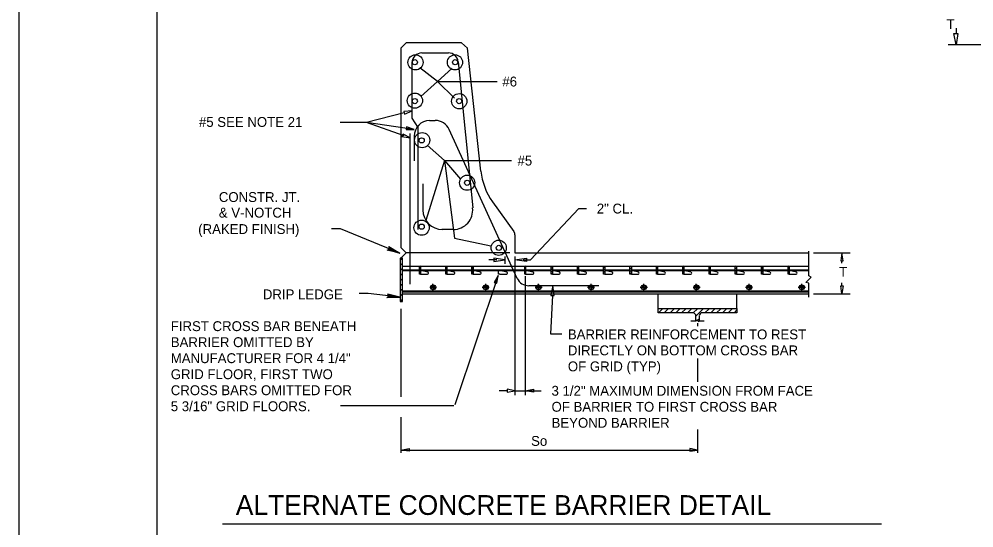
# Model space of a CAD drawing. Extents: x -24512 to -22484, y 4569 to 6351.
# Drawn here: x -24179.8 to -23889.5, y 5907.1 to 6061.6 of the extents above; entities that cross this region are included whole.
import ezdxf

# ---------------------------------------------------------------- set-up
doc = ezdxf.new("R2010")
doc.units = 0
for name, color, linetype in [('10', 7, 'Continuous'), ('11', 7, 'Continuous'), ('2', 7, 'Continuous'), ('4', 7, 'Continuous'), ('5', 7, 'Continuous'), ('8', 7, 'Continuous'), ('PLT-BNDY', 7, 'Continuous')]:
    doc.layers.add(name, color=color, linetype=linetype)

# ---------------------------------------------------------------- blocks, each defined once
blk = doc.blocks.new('JUQ000')
at = {"layer": '4'}
for p, q in [((71.0975, 21.771125), (71.421875, 22.095625)), ((71.237875, 21.6265), (71.566625, 21.95525))]:
    blk.add_line(p, q, dxfattribs=at)
blk = doc.blocks.new('JUQ002')
at = {"layer": '4'}
for p, q in [((72.87075, 24.39975), (72.993375, 24.522375)), ((72.87075, 24.114625), (73.021875, 24.265875)), ((72.87075, 23.8295), (73.021875, 23.98075)), ((72.87075, 23.544375), (73.021875, 23.695625))]:
    blk.add_line(p, q, dxfattribs=at)
blk = doc.blocks.new('JUQ004')
at = {"layer": '4'}
for p, q in [((69.644875, 24.310375), (69.796125, 24.4615)), ((69.644875, 24.02525), (69.796125, 24.176375)), ((69.644875, 23.740125), (69.796125, 23.89125)), ((69.70425, 23.514375), (69.796125, 23.60625))]:
    blk.add_line(p, q, dxfattribs=at)
blk = doc.blocks.new('JUQ003')
at = {"layer": '4'}
for p, q in [((89.35625, 63.69525), (89.860375, 64.19925)), ((90.069125, 63.69525), (90.573125, 64.19925)), ((90.781875, 63.69525), (91.285875, 64.19925)), ((91.49475, 63.69525), (91.99875, 64.19925)), ((92.2075, 63.69525), (92.7115, 64.19925)), ((92.920375, 63.69525), (93.424375, 64.19925)), ((93.628875, 63.691), (94.137125, 64.19925)), ((93.972625, 63.321875), (94.85, 64.19925)), ((95.05875, 63.69525), (95.56275, 64.19925)), ((95.7715, 63.69525), (96.275625, 64.19925)), ((96.484375, 63.69525), (96.988375, 64.19925)), ((97.197125, 63.69525), (97.70125, 64.19925)), ((97.91, 63.69525), (98.414, 64.19925)), ((98.62275, 63.69525), (99.014, 64.0865)), ((94.121125, 62.757625), (94.377, 63.013375))]:
    blk.add_line(p, q, dxfattribs=at)
blk = doc.blocks.new('JUQ001')
at = {"layer": '4'}
for p, q in [((66.419125, 24.506), (66.4355, 24.522375)), ((66.419125, 24.220875), (66.570375, 24.372125)), ((66.419125, 23.93575), (66.570375, 24.087)), ((66.419125, 23.650625), (66.570375, 23.801875)), ((66.567875, 23.514375), (66.570375, 23.51675))]:
    blk.add_line(p, q, dxfattribs=at)
blk = doc.blocks.new('_X')
at = {"layer": '4'}
for p, q in [((63.193375, 24.416625), (63.299125, 24.522375)), ((63.193375, 24.1315), (63.3445, 24.282625)), ((63.193375, 23.846375), (63.3445, 23.9975)), ((63.193375, 23.56125), (63.3445, 23.712375))]:
    blk.add_line(p, q, dxfattribs=at)

msp = doc.modelspace()

# ---------------------------------------------------------------- linework, layer by layer
at = {"layer": '10'}
for p, q in [((-23894.94, 6058.82), (-23894.94, 6057.27)), ((-23886.34, 6053.78), (-23897.31, 6053.78)), ((-24052.61, 6042.62), (-24057.96, 6046.8)), ((-24052.61, 6042.62), (-24048.18, 6046.62)), ((-24052.61, 6042.62), (-24057.6, 6038.13)), ((-24052.61, 6042.62), (-24034.39, 6042.62)), ((-24052.61, 6042.62), (-24047.44, 6037.57)), ((-24062.68, 6033.11), (-24074.15, 6030.24)), ((-24074.15, 6030.24), (-24082.14, 6030.24)), ((-24074.15, 6030.24), (-24076.52, 6030.24)), ((-24059.72, 6028.07), (-24074.15, 6030.24)), ((-24062.68, 6026.13), (-24074.15, 6030.24)), ((-24054.99, 6030.81), (-24053.26, 6030.81)), ((-24050.4, 6018.63), (-24055.75, 6023.36)), ((-24050.4, 6018.63), (-24056.12, 6000.47)), ((-24050.4, 6018.63), (-24030.09, 6018.63)), ((-24050.4, 6018.63), (-24045.6, 6013.02)), ((-24050.4, 6018.63), (-24047.44, 5995.12)), ((-24024.28, 5988.47), (-24009.57, 6004.13)), ((-24009.57, 6004.13), (-24007.32, 6004.13)), ((-24082.04, 5997.9), (-24084.78, 5997.9)), ((-24064.03, 5990.55), (-24082.04, 5997.9)), ((-24047.44, 5995.12), (-24036.37, 5992.72)), ((-23938.25, 5990.59), (-23927.15, 5990.59)), ((-24034.5, 5988.47), (-24037, 5988.47)), ((-24032.13, 5989.51), (-24032.13, 5987.23)), ((-24029.02, 5989.47), (-24029.02, 5947.45)), ((-24026.52, 5988.47), (-24024.28, 5988.47)), ((-23929.64, 5987.48), (-23929.64, 5988.23)), ((-24034.18, 5983.7), (-24047.28, 5944.42)), ((-24025.9, 5983.49), (-24025.9, 5947.45)), ((-24054.45, 5980.12), (-24054.95, 5980.12)), ((-24053.58, 5980.12), (-24054.2, 5980.12)), ((-24053.96, 5980.74), (-24053.96, 5981.24)), ((-24053.96, 5979.87), (-24053.96, 5980.37)), ((-24053.96, 5979.12), (-24053.96, 5979.5)), ((-24052.83, 5980.12), (-24053.33, 5980.12)), ((-24038.49, 5980.12), (-24038.99, 5980.12)), ((-24037.62, 5980.12), (-24038.12, 5980.12)), ((-24037.87, 5980.74), (-24037.87, 5981.24)), ((-24037.87, 5979.87), (-24037.87, 5980.37)), ((-24037.87, 5979.12), (-24037.87, 5979.5)), ((-24036.87, 5980.12), (-24037.25, 5980.12)), ((-24022.41, 5980.12), (-24022.91, 5980.12)), ((-24021.66, 5980.12), (-24022.16, 5980.12)), ((-24021.91, 5980.74), (-24021.91, 5981.24)), ((-24021.91, 5979.87), (-24021.91, 5980.37)), ((-24021.91, 5979.12), (-24021.91, 5979.5)), ((-24020.79, 5980.12), (-24021.29, 5980.12)), ((-24006.45, 5980.12), (-24006.95, 5980.12)), ((-24005.58, 5980.12), (-24006.08, 5980.12)), ((-24005.83, 5980.74), (-24005.83, 5981.24)), ((-24005.83, 5979.87), (-24005.83, 5980.37)), ((-24005.83, 5979.12), (-24005.83, 5979.5)), ((-24004.83, 5980.12), (-24005.33, 5980.12)), ((-23990.49, 5980.12), (-23990.99, 5980.12)), ((-23989.62, 5980.12), (-23990.12, 5980.12)), ((-23989.87, 5980.74), (-23989.87, 5981.24)), ((-23989.87, 5979.87), (-23989.87, 5980.37)), ((-23989.87, 5979.12), (-23989.87, 5979.5)), ((-23988.74, 5980.12), (-23989.37, 5980.12)), ((-23974.4, 5980.12), (-23974.9, 5980.12)), ((-23973.53, 5980.12), (-23974.16, 5980.12)), ((-23973.91, 5980.74), (-23973.91, 5981.24)), ((-23973.91, 5979.87), (-23973.91, 5980.37)), ((-23973.91, 5979.12), (-23973.91, 5979.5)), ((-23972.78, 5980.12), (-23973.28, 5980.12)), ((-23958.44, 5980.12), (-23958.94, 5980.12)), ((-23957.57, 5980.12), (-23958.2, 5980.12)), ((-23957.82, 5980.74), (-23957.82, 5981.24)), ((-23957.82, 5979.87), (-23957.82, 5980.37)), ((-23957.82, 5979.12), (-23957.82, 5979.5)), ((-23956.82, 5980.12), (-23957.32, 5980.12)), ((-23942.36, 5980.12), (-23942.98, 5980.12)), ((-23941.61, 5980.12), (-23942.11, 5980.12)), ((-23941.86, 5980.74), (-23941.86, 5981.24)), ((-23941.86, 5979.87), (-23941.86, 5980.37)), ((-23941.86, 5979.12), (-23941.86, 5979.5)), ((-23940.74, 5980.12), (-23941.24, 5980.12)), ((-23929.64, 5980.62), (-23929.64, 5981.49)), ((-24073.66, 5978.25), (-24076.4, 5978.25)), ((-24064.03, 5977.16), (-24073.66, 5978.25)), ((-24017.61, 5977.63), (-24018.23, 5966.03)), ((-23938.25, 5978.13), (-23927.15, 5978.13)), ((-24063.68, 5973.66), (-24063.68, 5946.93)), ((-23973.53, 5969.27), (-23973.53, 5968.4)), ((-24018.23, 5966.03), (-24014.74, 5966.03)), ((-23973.53, 5958.55), (-23973.53, 5951.44)), ((-24031.39, 5948.7), (-24033.88, 5948.7)), ((-24029.02, 5948.7), (-24021.04, 5948.7)), ((-24047.62, 5944.19), (-24082.03, 5944.19)), ((-24063.68, 5940.76), (-24063.68, 5929.87)), ((-23973.53, 5936.98), (-23973.53, 5929.87)), ((-24063.68, 5930.74), (-23973.53, 5930.74))]:
    msp.add_line(p, q, dxfattribs=at)
for points in [[(-23895.64, 6057.27), (-23894.42, 6057.27), (-23894.94, 6053.78)], [(-24062.81, 6033.49), (-24062.56, 6032.74), (-24060.31, 6033.74)], [(-24061.98, 6028.89), (-24062.06, 6028.02), (-24059.67, 6028.06)], [(-24063.02, 6026.7), (-24063.4, 6025.95), (-24060.9, 6025.57)], [(-23930.02, 5988.23), (-23929.27, 5988.23), (-23929.64, 5990.59)], [(-24035.45, 5989), (-24035.45, 5987.95), (-24032.13, 5988.47)], [(-24025.53, 5989), (-24025.53, 5987.95), (-24029.02, 5988.47)], [(-24035.33, 5981.6), (-24034.53, 5981.36), (-24034.18, 5983.7)], [(-24018.1, 5977.63), (-24017.11, 5977.63), (-24017.48, 5980.74)], [(-23930.02, 5980.62), (-23929.27, 5980.62), (-23929.64, 5978.13)], [(-24031.39, 5949.2), (-24031.39, 5948.33), (-24029.02, 5948.7)], [(-24023.41, 5949.2), (-24023.41, 5948.33), (-24025.9, 5948.7)], [(-24061.19, 5931.24), (-24061.19, 5930.37), (-24063.68, 5930.74)], [(-23975.9, 5931.24), (-23975.9, 5930.37), (-23973.53, 5930.74)]]:
    msp.add_lwpolyline(points, close=True, dxfattribs=at)
for points in [[(-24067.27, 5992.37), (-24067.24, 5992.07), (-24064.03, 5990.55), (-24067.27, 5992.37), (-24067.38, 5992.59), (-24064.03, 5990.55), (-24067.38, 5991.73), (-24067.6, 5991.53), (-24064.03, 5990.55), (-24067.85, 5991.44), (-24067.6, 5991.53)], [(-24067.64, 5978.03), (-24067.53, 5977.75), (-24064.03, 5977.16), (-24067.64, 5978.03), (-24067.81, 5978.22), (-24064.03, 5977.16), (-24067.57, 5977.38), (-24067.73, 5977.13), (-24064.03, 5977.16), (-24067.95, 5976.98), (-24067.73, 5977.13)]]:
    msp.add_lwpolyline(points, dxfattribs=at)
for centre in [(-24059.26, 6048.46), (-24047.26, 6048.46), (-24059.44, 6036.83), (-24045.97, 6036.65), (-24057.23, 6024.84), (-24043.57, 6011.91), (-24057.41, 5998.25), (-24033.97, 5992.16)]:
    msp.add_circle(centre, 2.31, dxfattribs=at)
for centre, radius, start, end in [((-24057.31, 6048.32), 3, 90, 180), ((-24049.26, 6048.32), 3, 5.6952, 90), ((-24054.84, 6026.02), 4.8, 91.8539, 180), ((-24053.3, 6026.01), 4.8, 26.0753, 89.5289), ((-24024.78, 5984.62), 4, 206.0755, 270)]:
    msp.add_arc(centre, radius, start, end, dxfattribs=at)
at = {"layer": '11'}
msp.add_line((-23917.58, 5908.21), (-24117.88, 5908.21), dxfattribs=at)
at = {"layer": '2'}
msp.add_line((-24137.79, 5772.04), (-24137.79, 6334.63), dxfattribs=at)
at = {"layer": '4'}
for p, q in [((-24063.94, 5988.48), (-24063.24, 5989.03)), ((-24063.94, 5986.92), (-24063.24, 5987.47)), ((-24063.94, 5985.37), (-24063.24, 5985.92)), ((-24063.94, 5983.81), (-24063.24, 5984.36)), ((-24063.94, 5982.25), (-24063.24, 5982.8)), ((-24063.94, 5980.7), (-24063.24, 5981.25)), ((-24063.94, 5979.14), (-24063.24, 5979.69)), ((-24063.94, 5977.59), (-24063.24, 5978.14)), ((-24063.94, 5976.03), (-24063.24, 5976.58))]:
    msp.add_line(p, q, dxfattribs=at)
at = {"layer": '5'}
for p, q in [((-24029.02, 5990.59), (-23939.74, 5990.59)), ((-24063.18, 5988.97), (-24063.88, 5988.97)), ((-24063.88, 5988.97), (-24063.88, 5975.81)), ((-24063.18, 5975.81), (-24063.18, 5988.97)), ((-24063.18, 5986.6), (-24058.07, 5986.6)), ((-24063.18, 5985.48), (-24058.07, 5985.48)), ((-24063.18, 5985.23), (-24058.07, 5985.23)), ((-24057.7, 5986.6), (-24050.09, 5986.6)), ((-24057.7, 5985.48), (-24050.09, 5985.48)), ((-24057.7, 5985.23), (-24050.09, 5985.23)), ((-24055.45, 5984.73), (-24057.7, 5985.23)), ((-24049.72, 5986.6), (-24042.11, 5986.6)), ((-24049.72, 5985.48), (-24042.11, 5985.48)), ((-24049.72, 5985.23), (-24042.11, 5985.23)), ((-24047.47, 5984.73), (-24049.72, 5985.23)), ((-24041.74, 5986.6), (-24034.01, 5986.6)), ((-24041.74, 5985.48), (-24034.01, 5985.48)), ((-24041.74, 5985.23), (-24034.01, 5985.23)), ((-24039.49, 5984.73), (-24041.74, 5985.23)), ((-24034.01, 5986.6), (-24026.03, 5986.6)), ((-24034.01, 5985.48), (-24026.03, 5985.48)), ((-24034.01, 5985.23), (-24026.03, 5985.23)), ((-24031.51, 5984.73), (-24033.63, 5985.23)), ((-24025.78, 5986.6), (-24018.05, 5986.6)), ((-24025.78, 5985.48), (-24018.05, 5985.48)), ((-24025.78, 5985.23), (-24018.05, 5985.23)), ((-24023.53, 5984.73), (-24025.78, 5985.23)), ((-24017.67, 5986.6), (-24010.07, 5986.6)), ((-24017.67, 5985.48), (-24010.07, 5985.48)), ((-24017.67, 5985.23), (-24010.07, 5985.23)), ((-24015.43, 5984.73), (-24017.67, 5985.23)), ((-24009.69, 5986.6), (-24002.09, 5986.6)), ((-24009.69, 5985.48), (-24002.09, 5985.48)), ((-24009.69, 5985.23), (-24002.09, 5985.23)), ((-24007.57, 5984.73), (-24009.69, 5985.23)), ((-24001.71, 5986.6), (-23994.11, 5986.6)), ((-24001.71, 5985.48), (-23994.11, 5985.48)), ((-24001.71, 5985.23), (-23994.11, 5985.23)), ((-23999.47, 5984.73), (-24001.71, 5985.23)), ((-23993.61, 5986.6), (-23986, 5986.6)), ((-23993.61, 5985.48), (-23986, 5985.48)), ((-23993.61, 5985.23), (-23986, 5985.23)), ((-23991.49, 5984.73), (-23993.61, 5985.23)), ((-23985.75, 5986.6), (-23978.02, 5986.6)), ((-23985.75, 5985.48), (-23978.02, 5985.48)), ((-23985.75, 5985.23), (-23978.02, 5985.23)), ((-23983.51, 5984.73), (-23985.75, 5985.23)), ((-23977.65, 5986.6), (-23970.04, 5986.6)), ((-23977.65, 5985.48), (-23970.04, 5985.48)), ((-23977.65, 5985.23), (-23970.04, 5985.23)), ((-23975.53, 5984.73), (-23977.65, 5985.23)), ((-23969.67, 5986.6), (-23962.06, 5986.6)), ((-23969.67, 5985.48), (-23962.06, 5985.48)), ((-23969.67, 5985.23), (-23962.06, 5985.23)), ((-23967.55, 5984.73), (-23969.67, 5985.23)), ((-23961.69, 5986.6), (-23954.08, 5986.6)), ((-23961.69, 5985.48), (-23954.08, 5985.48)), ((-23961.69, 5985.23), (-23954.08, 5985.23)), ((-23959.44, 5984.73), (-23961.69, 5985.23)), ((-23953.71, 5986.6), (-23945.98, 5986.6)), ((-23953.71, 5985.48), (-23945.98, 5985.48)), ((-23953.71, 5985.23), (-23945.98, 5985.23)), ((-23951.59, 5984.73), (-23953.71, 5985.23)), ((-23945.73, 5986.6), (-23939.74, 5986.6)), ((-23945.73, 5985.48), (-23939.74, 5985.48)), ((-23945.73, 5985.23), (-23939.74, 5985.23)), ((-23943.48, 5984.73), (-23945.73, 5985.23)), ((-24057.7, 5984.11), (-24055.58, 5984.11)), ((-24049.72, 5984.11), (-24047.6, 5984.11)), ((-24041.74, 5984.11), (-24039.62, 5984.11)), ((-24033.63, 5984.11), (-24031.51, 5984.11)), ((-24025.78, 5984.11), (-24023.53, 5984.11)), ((-24017.67, 5984.11), (-24015.55, 5984.11)), ((-24009.69, 5984.11), (-24007.57, 5984.11)), ((-24001.71, 5984.11), (-23999.59, 5984.11)), ((-23993.61, 5984.11), (-23991.49, 5984.11)), ((-23985.75, 5984.11), (-23983.63, 5984.11)), ((-23977.65, 5984.11), (-23975.53, 5984.11)), ((-23969.67, 5984.11), (-23967.55, 5984.11)), ((-23961.69, 5984.11), (-23959.57, 5984.11)), ((-23953.71, 5984.11), (-23951.59, 5984.11)), ((-23945.73, 5984.11), (-23943.61, 5984.11)), ((-24063.18, 5979.12), (-23939.74, 5979.12)), ((-24063.18, 5978.75), (-23939.74, 5978.75)), ((-24063.88, 5975.81), (-24063.18, 5975.81)), ((-24063.18, 5978.13), (-23939.74, 5978.13)), ((-23985.5, 5973.76), (-23985.5, 5978.13)), ((-23961.56, 5973.76), (-23961.56, 5978.13)), ((-23985.5, 5972.39), (-23985.5, 5973.76)), ((-23985.5, 5973.76), (-23961.56, 5973.76)), ((-23961.56, 5973.76), (-23961.56, 5972.39)), ((-23975.03, 5972.39), (-23985.5, 5972.39)), ((-23975.53, 5970.02), (-23974.03, 5970.02)), ((-23974.03, 5970.02), (-23974.03, 5971.39)), ((-23973.03, 5971.39), (-23973.03, 5970.02)), ((-23973.03, 5970.02), (-23971.54, 5970.02)), ((-23961.56, 5972.39), (-23972.04, 5972.39))]:
    msp.add_line(p, q, dxfattribs=at)
for points in [[(-23939.74, 5977.13), (-23939.74, 5981.37), (-23940.61, 5981.62), (-23938.99, 5983.24), (-23939.74, 5983.61), (-23939.74, 5991.09)], [(-24033.63, 5984.11), (-24034.01, 5984.11), (-24034.01, 5985.23)], [(-23974.03, 5970.02), (-23973.91, 5970.02), (-23973.78, 5970.27), (-23973.16, 5969.65), (-23973.16, 5970.02), (-23973.03, 5970.02)], [(-23974.03, 5970.02), (-23973.91, 5970.02), (-23973.78, 5970.27), (-23973.16, 5969.65), (-23973.16, 5970.02), (-23973.03, 5970.02)]]:
    msp.add_lwpolyline(points, dxfattribs=at)
for points in [[(-24057.7, 5986.6), (-24057.7, 5984.11), (-24058.07, 5984.11), (-24058.07, 5986.6)], [(-24049.72, 5986.6), (-24049.72, 5984.11), (-24050.09, 5984.11), (-24050.09, 5986.6)], [(-24041.74, 5986.6), (-24041.74, 5984.11), (-24042.11, 5984.11), (-24042.11, 5986.6)], [(-24025.78, 5986.6), (-24025.78, 5984.11), (-24026.03, 5984.11), (-24026.03, 5986.6)], [(-24017.67, 5986.6), (-24017.67, 5984.11), (-24018.05, 5984.11), (-24018.05, 5986.6)], [(-24009.69, 5986.6), (-24009.69, 5984.11), (-24010.07, 5984.11), (-24010.07, 5986.6)], [(-24001.71, 5986.6), (-24001.71, 5984.11), (-24002.09, 5984.11), (-24002.09, 5986.6)], [(-23993.61, 5986.6), (-23993.61, 5984.11), (-23994.11, 5984.11), (-23994.11, 5986.6)], [(-23985.75, 5986.6), (-23985.75, 5984.11), (-23986, 5984.11), (-23986, 5986.6)], [(-23977.65, 5986.6), (-23977.65, 5984.11), (-23978.02, 5984.11), (-23978.02, 5986.6)], [(-23969.67, 5986.6), (-23969.67, 5984.11), (-23970.04, 5984.11), (-23970.04, 5986.6)], [(-23961.69, 5986.6), (-23961.69, 5984.11), (-23962.06, 5984.11), (-23962.06, 5986.6)], [(-23953.71, 5986.6), (-23953.71, 5984.11), (-23954.08, 5984.11), (-23954.08, 5986.6)], [(-23945.73, 5986.6), (-23945.73, 5984.11), (-23945.98, 5984.11), (-23945.98, 5986.6)]]:
    msp.add_lwpolyline(points, close=True, dxfattribs=at)
for centre, radius in [((-24053.88, 5980.15), 0.75), ((-24053.88, 5980.02), 0.625), ((-24037.88, 5980.15), 0.75), ((-24037.88, 5980.02), 0.625), ((-24021.87, 5980.15), 0.75), ((-24021.87, 5980.02), 0.625), ((-24005.87, 5980.15), 0.75), ((-24005.87, 5980.02), 0.625), ((-23989.87, 5980.15), 0.75), ((-23989.87, 5980.02), 0.625), ((-23973.87, 5980.15), 0.75), ((-23973.87, 5980.02), 0.625), ((-23957.86, 5980.15), 0.75), ((-23957.86, 5980.02), 0.625), ((-23941.86, 5980.15), 0.75), ((-23941.86, 5980.02), 0.625)]:
    msp.add_circle(centre, radius, dxfattribs=at)
for centre, radius, start, end in [((-24055.59, 5984.43), 0.305, 271.249, 76.5605), ((-24047.59, 5984.43), 0.305, 271.249, 76.5605), ((-24039.59, 5984.43), 0.305, 271.249, 76.5605), ((-24031.59, 5984.43), 0.305, 271.249, 76.5605), ((-24023.59, 5984.43), 0.305, 271.249, 76.5605), ((-24015.58, 5984.43), 0.305, 271.249, 76.5605), ((-24007.58, 5984.43), 0.305, 271.249, 76.5605), ((-23999.58, 5984.43), 0.305, 271.249, 76.5605), ((-23991.58, 5984.43), 0.305, 271.249, 76.5605), ((-23983.58, 5984.43), 0.305, 271.249, 76.5605), ((-23975.58, 5984.43), 0.305, 271.249, 76.5605), ((-23967.58, 5984.43), 0.305, 271.249, 76.5605), ((-23959.58, 5984.43), 0.305, 271.249, 76.5605), ((-23951.57, 5984.43), 0.305, 271.249, 76.5605), ((-23943.57, 5984.43), 0.305, 271.249, 76.5605), ((-23975.02, 5971.44), 1, 0, 90), ((-23972.02, 5971.44), 1, 90, 180)]:
    msp.add_arc(centre, radius, start, end, dxfattribs=at)
at = {"layer": '8'}
for p, q in [((-24057.31, 6051.32), (-24049.26, 6051.32)), ((-24060.31, 6031.49), (-24060.31, 6048.32)), ((-24046.28, 6048.61), (-24041.86, 6004.31)), ((-24058.43, 5997.7), (-24058.43, 6028.66)), ((-24028.37, 5982.86), (-24048.99, 6028.12)), ((-24060.84, 5981.14), (-24060.84, 6026.88)), ((-24059.64, 6026.02), (-24059.64, 6018.56)), ((-24056.95, 6003.69), (-24056.95, 6011.54)), ((-24047.72, 5997.7), (-24051.21, 5997.7)), ((-24003.58, 5980.62), (-24024.78, 5980.62))]:
    msp.add_line(p, q, dxfattribs=at)
msp.add_lwpolyline([(-24058.43, 6028.66), (-24060.31, 6031.49)], dxfattribs=at)
for centre in [(-24059.49, 6048.51), (-24047.19, 6048.51), (-24059.49, 6036.7), (-24045.98, 6036.7), (-24057.39, 6024.76), (-24043.53, 6011.9), (-24057.39, 5998.56), (-24033.91, 5992.13)]:
    msp.add_circle(centre, 0.788, dxfattribs=at)
for centre, start, end in [((-24051.12, 6003.62), 180, 270), ((-24047.78, 6003.62), 270, 6.0946)]:
    msp.add_arc(centre, 5.91, start, end, dxfattribs=at)
at = {"layer": 'PLT-BNDY'}
for p, q in [((-24063.68, 6052.81), (-24062.06, 6054.43)), ((-24045.23, 6054.43), (-24062.06, 6054.43)), ((-24043.48, 6052.81), (-24045.23, 6054.43)), ((-24063.68, 6052.81), (-24063.68, 5992.22)), ((-24039.37, 6015.41), (-24043.48, 6052.81)), ((-24035.88, 6006.06), (-24029.39, 5997.08)), ((-24029.02, 5995.96), (-24029.02, 5990.59)), ((-24063.68, 5992.22), (-24062.06, 5990.59)), ((-24063.68, 5988.97), (-24062.06, 5990.59)), ((-24030.55, 5990.59), (-24062.06, 5990.59))]:
    msp.add_line(p, q, dxfattribs=at)
msp.add_lwpolyline([(-23338.75, 5757.04), (-24179.75, 5757.04), (-24179.75, 6351.04), (-23338.75, 6351.04)], close=True, dxfattribs=at)
for centre, radius, start, end in [((-24019.82, 6017.55), 19.69, 186.1155, 215.5377), ((-24030.97, 5995.9), 1.97, 0, 35.5377)]:
    msp.add_arc(centre, radius, start, end, dxfattribs=at)

# ---------------------------------------------------------------- block references
at = {"layer": '4', "xscale": 2.4803976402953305, "yscale": 2.4803976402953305}
for name, p in [('_X', (-24214.8, 5925.88)), ('JUQ001', (-24214.8, 5925.88)), ('JUQ001', (-24206.82, 5925.88)), ('JUQ002', (-24206.82, 5925.88)), ('JUQ004', (-24190.74, 5925.88)), ('JUQ002', (-24190.74, 5925.88)), ('JUQ004', (-24174.78, 5925.88)), ('JUQ002', (-24174.78, 5925.88)), ('JUQ004', (-24158.82, 5925.88)), ('JUQ002', (-24158.82, 5925.88)), ('JUQ004', (-24142.86, 5925.88)), ('JUQ002', (-24142.86, 5925.88)), ('JUQ004', (-24126.77, 5925.88)), ('JUQ002', (-24126.77, 5925.88)), ('JUQ000', (-24230.76, 5925.88)), ('JUQ000', (-24214.8, 5925.88)), ('JUQ000', (-24198.84, 5925.88)), ('JUQ000', (-24182.88, 5925.88)), ('JUQ000', (-24166.8, 5925.88)), ('JUQ000', (-24150.84, 5925.88)), ('JUQ000', (-24134.75, 5925.88)), ('JUQ000', (-24118.79, 5925.88)), ('JUQ003', (-24207.07, 5814.41))]:
    msp.add_blockref(name, p, dxfattribs=at)

# ---------------------------------------------------------------- texts
at = {"layer": '10'}
for s, p in [('T', (-23897.85, 6058.54)), ('#6', (-24032.86, 6041.13)), ('#5 SEE NOTE 21', (-24125.09, 6028.85)), ('#5', (-24028.25, 6017.13)), ('CONSTR. JT.', (-24119.04, 6006.06)), ('2" CL.', (-24004.15, 6002.56)), ('& V-NOTCH', (-24119.04, 6001.32)), ('(RAKED FINISH)', (-24125.31, 5996.33)), ('T', (-23930.49, 5983.35)), ('DRIP LEDGE', (-24105.66, 5976.52)), ('FIRST CROSS BAR BENEATH ', (-24133.65, 5966.85)), ('BARRIER REINFORCEMENT TO REST ', (-24012.95, 5964.36)), ('BARRIER OMITTED BY ', (-24133.65, 5961.99)), ('DIRECTLY ON BOTTOM CROSS BAR ', (-24012.95, 5959.5)), ('MANUFACTURER FOR 4 1/4"', (-24133.65, 5957.13)), ('OF GRID (TYP)', (-24012.95, 5954.64)), ('GRID FLOOR, FIRST TWO ', (-24133.65, 5952.26)), ('CROSS BARS OMITTED FOR ', (-24133.65, 5947.4)), ('3 1/2" MAXIMUM DIMENSION FROM FACE ', (-24017.91, 5947.23)), ('5 3/16" GRID FLOORS.', (-24133.65, 5942.54)), ('OF BARRIER TO FIRST CROSS BAR ', (-24017.91, 5942.37)), ('BEYOND BARRIER', (-24017.91, 5937.51)), ('So', (-24024.12, 5932.01))]:
    msp.add_text(s, height=3, dxfattribs=at).set_placement(p)
at = {"layer": '11'}
msp.add_text('ALTERNATE CONCRETE BARRIER DETAIL', height=6.0008, dxfattribs=at).set_placement((-24113.89, 5911.04))

doc.saveas('drawing.dxf')
